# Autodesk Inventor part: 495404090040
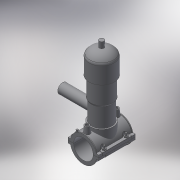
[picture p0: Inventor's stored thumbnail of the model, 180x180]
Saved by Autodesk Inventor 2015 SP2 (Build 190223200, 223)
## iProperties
Created: 2017-07
Part Number: 495404090040
Material: Generic
Description: PLASSON TAPPING VALVE 90-40
Document SubType Name: Modeling
Designer: KIM
Density: 1 g/cm^3
Appearance: Default
Author: KIM
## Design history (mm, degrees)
derived "495404-4954S4.ipt"
feature "Solid1::495404-4954S4.ipt"
feature "Solid2::495404-4954S4.ipt"
tag "TaggingFeature1"
body "Solid1"
body "Solid2"
other parameters: "d2" = 126, "d3" = 22.5, "d4" = 118, "d5" = 0, "d6" = 0.1, "d8" = 0, "d19" = 6, "d20" = 6, "d21" = 70.8, "d23" = 0, "d24" = 35.4, "d26" = 0, "d27" = 3, "d28" = 3, "d29" = 3, "d31" = 6, "d32" = 0, "d33" = 0, "d34" = 0.6, "d40" = 60.84, "d47" = 104.5, "d70" = 15, "d72" = 0, "d73" = 6, "d75" = 5, "d76" = 0, "d77" = 4.5, "d78" = 75, "d79" = 15, "d80" = 47.2, "d82" = 5 deg, "d84" = 4, "d85" = 14, "d86" = 0, "d87" = 3, "d88" = 0, "d89" = 1, "d90" = 1, "d91" = 94.4, "d92" = 0, "d93" = 0.5, "d94" = 47.36842, "d96" = 120.51, "d97" = 2.36, "d98" = 0, "d120" = 140 deg, "d121" = 24.228, "d122" = 20 deg, "d123" = 234, "d124" = 70.2, "d126" = 0, "d143" = 92.7, "d145" = 20.76923, "d149" = 1.35, "d150" = 22.84615, "d153" = 118, "d154" = 0, "d156" = 58.5, "d157" = 160 deg, "d159" = 5.4, "d161" = 1.35, "d162" = 70.8, "d163" = 0, "d164" = 45, "d167" = 9, "d168" = 57.07317, "d170" = 3, "d172" = 0, "d173" = 1, "d175" = 45, "d176" = 20 deg, "d177" = 6.3, "d178" = 27, "d180" = 0, "d183" = 10.8, "d184" = 5.04, "d185" = 38.35, "d186" = 38.35, "d187" = 58.5, "d188" = 8.1, "d189" = 6.3, "d190" = 0, "d191" = 87.75, "d193" = 6.8, "d194" = 2.95, "d195" = 90 deg, "d197" = 0, "d199" = 0, "d205" = 14.64, "d206" = 81.33333, "d207" = 244, "d208" = 224.48, "d209" = 207.4, "d210" = 200.08, "d211" = 146.4, "d212" = 85.4, "d213" = 65.88, "d214" = 73.2, "d216" = 19.52, "d217" = 70.76, "d218" = 80.52, "d222" = 0, "d223" = 117, "d224" = 137, "d225" = 46, "d229" = 137, "d230" = 0, "B_" = 126, "H_" = 137, "L_" = 118, "d_t" = 6, "H_1" = 46, "H_2" = 244, "d148" = 1.35, "d160" = 1.35, "d169" = 3, "d192" = 6.8, "d228" = 32
